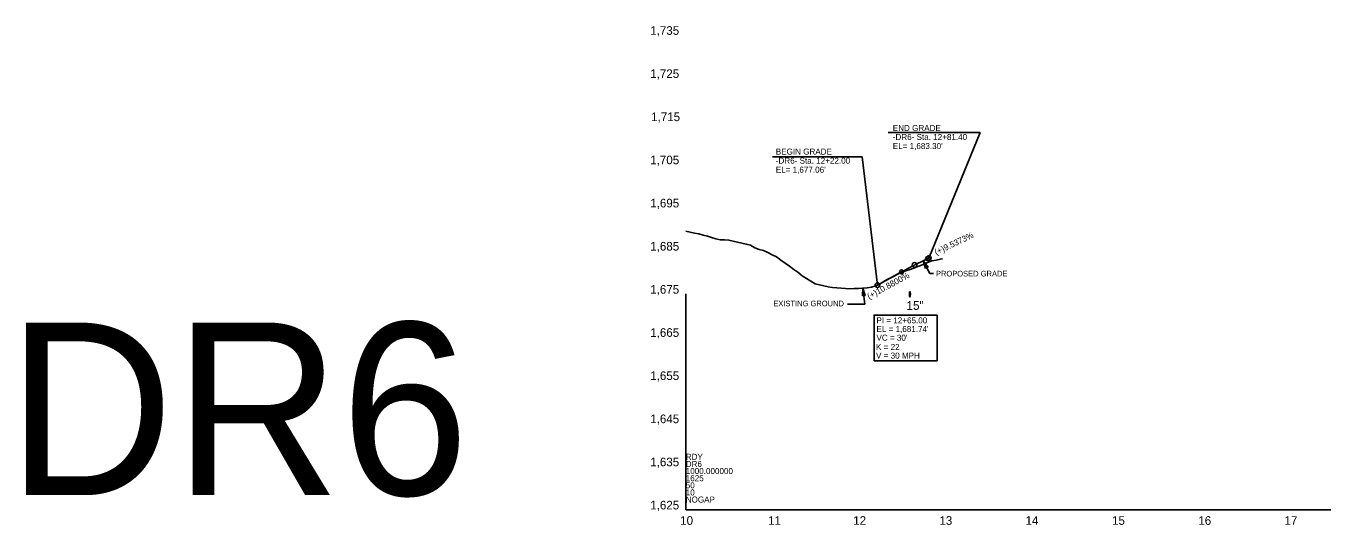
# Model space of a CAD drawing. Extents: x 498575 to 532350, y 405181 to 484585.
# Drawn here: x 526520 to 528031, y 469470 to 470048 of the extents above; entities that cross this region are included whole.
import ezdxf

# ---------------------------------------------------------------- set-up
doc = ezdxf.new("R2010")
doc.units = 0
for name, color, linetype in [('Exist Profile Cell', 7, 'Continuous'), ('Exist Vertical Profile Ground Line', 7, 'Continuous'), ('Exist Vertical Profile Horizontal Axis Label Major', 7, 'Continuous'), ('Exist Vertical Profile Vertical Axis Label', 7, 'Continuous'), ('Prop Drainage Structure Pipe Welded Steel 54in Label', 7, 'Continuous'), ('Prop Grid Mask', 7, 'Continuous'), ('Prop PFL Text', 7, 'Continuous'), ('Prop Vertical Profile Curve Label', 7, 'Continuous'), ('Prop Vertical Profile Grade', 7, 'Continuous'), ('Prop Vertical Profile Grade Label', 7, 'Continuous'), ('Prop VPI Label', 7, 'Continuous'), ('Scratch_Level_7', 7, 'Continuous')]:
    doc.layers.add(name, color=color, linetype=linetype)

msp = doc.modelspace()

# ---------------------------------------------------------------- linework, layer by layer
at = {"layer": 'Exist Profile Cell'}
for q in [(527283.8, 469737.3), (528031, 469487.3), (527283.8, 469487.3)]:
    msp.add_line((527283.8, 469487.3), q, dxfattribs=at)
at = {"layer": 'Exist Vertical Profile Ground Line'}
msp.add_lwpolyline([(527283.8, 469810.2), (527288.8, 469809.1), (527293.8, 469807.9), (527298.8, 469806.8), (527303.8, 469805.6), (527308.8, 469804.1), (527313.8, 469802.6), (527318.8, 469801.3), (527323.8, 469800.1), (527328.8, 469800), (527333.8, 469799.8), (527338.8, 469798.6), (527343.8, 469797.4), (527348.8, 469796.3), (527353.8, 469795.2), (527358.8, 469793.7), (527363.8, 469790.9), (527368.8, 469789), (527373.8, 469787.6), (527378.8, 469785.4), (527383.8, 469782.7), (527388.8, 469780.2), (527393.8, 469776.5), (527398.8, 469773), (527403.8, 469769.5), (527408.8, 469765.7), (527413.8, 469762.6), (527418.8, 469758.5), (527423.8, 469755.3), (527428.8, 469752), (527433.8, 469749.1), (527438.8, 469747.9), (527443.8, 469746.7), (527448.8, 469745.7), (527453.8, 469744.9), (527458.8, 469744.4), (527463.8, 469743.9), (527468.8, 469743.6), (527473.8, 469743.3), (527478.8, 469743.5), (527483.8, 469743.7), (527488.8, 469744.2), (527493.8, 469744.5), (527498.8, 469745.1), (527503.8, 469746.6), (527508.8, 469749.2), (527513.8, 469752.1), (527518.8, 469754.7), (527523.8, 469757.3), (527528.8, 469759.9), (527533.8, 469762.5), (527538.8, 469764.2), (527543.8, 469765.8), (527548.8, 469767.6), (527553.8, 469769.5), (527558.8, 469771.5), (527563.8, 469773.7), (527568.8, 469775.6), (527573.8, 469776.6), (527578.8, 469777.7), (527581.3, 469778.2)], dxfattribs=at)
at = {"layer": 'Prop Drainage Structure Pipe Welded Steel 54in Label'}
msp.add_ellipse((527543.4, 469737), major_axis=(0, 3.12), ratio=0.2, dxfattribs=at)
at = {"layer": 'Prop Grid Mask'}
msp.add_lwpolyline([(527502, 469659.8), (527575, 469659.8), (527575, 469712.9), (527502, 469712.9)], close=True, dxfattribs=at)
at = {"layer": 'Prop PFL Text'}
for p, q in [((527558.6, 469775.7), (527566.5, 469761.2)), ((527570.6, 469761.2), (527566.5, 469761.2)), ((527491.4, 469725.5), (527488.8, 469744.2)), ((527471, 469725.5), (527491.4, 469725.5))]:
    msp.add_line(p, q, dxfattribs=at)
for points in [[(527561.6, 469767), (527558.6, 469775.7), (527564.4, 469768.5), (527562.4, 469768.7)], [(527488.5, 469735), (527488.8, 469744.2), (527491.6, 469735.4), (527489.9, 469736.3)]]:
    msp.add_lwpolyline(points, close=True, dxfattribs=at)
at = {"layer": 'Prop Vertical Profile Curve Label'}
for centre in [(527563.8, 469778.2), (527533.8, 469762.9)]:
    msp.add_circle(centre, 2.25, dxfattribs=at)
at = {"layer": 'Prop Vertical Profile Grade'}
for p, q in [((527563.8, 469778.2), (527565.2, 469778.8)), ((527505.8, 469747.6), (527533.8, 469762.9))]:
    msp.add_line(p, q, dxfattribs=at)
msp.add_spline([(527533.8, 469762.9), (527534.4, 469763.2), (527535, 469763.5), (527535.6, 469763.8), (527536.2, 469764.2), (527536.8, 469764.5), (527537.4, 469764.8), (527538, 469765.1), (527538.6, 469765.4), (527539.2, 469765.8), (527539.8, 469766.1), (527540.4, 469766.4), (527541, 469766.7), (527541.6, 469767), (527542.2, 469767.3), (527542.8, 469767.7), (527543.4, 469768), (527544, 469768.3), (527544.6, 469768.6), (527545.2, 469768.9), (527545.8, 469769.2), (527546.4, 469769.5), (527547, 469769.8), (527547.6, 469770.1), (527548.2, 469770.5), (527548.8, 469770.8), (527549.4, 469771.1), (527550, 469771.4), (527550.6, 469771.7), (527551.2, 469772), (527551.8, 469772.3), (527552.4, 469772.6), (527553, 469772.9), (527553.6, 469773.2), (527554.2, 469773.5), (527554.8, 469773.8), (527555.4, 469774.1), (527556, 469774.4), (527556.6, 469774.7), (527557.2, 469775), (527557.8, 469775.3), (527558.4, 469775.6), (527559, 469775.9), (527559.6, 469776.1), (527560.2, 469776.4), (527560.8, 469776.7), (527561.4, 469777), (527562, 469777.3), (527562.6, 469777.6), (527563.2, 469777.9), (527563.8, 469778.2)], degree=3, dxfattribs=at)
at = {"layer": 'Prop VPI Label'}
for p, q in [((527518.2, 469924.6), (527624.7, 469924.6)), ((527565.2, 469778.8), (527624.7, 469924.6)), ((527384.4, 469896.3), (527488, 469896.3)), ((527488, 469896.3), (527505.8, 469747.6)), ((527533.8, 469762.9), (527546.4, 469769.7)), ((527563.8, 469778.2), (527551.3, 469772.2))]:
    msp.add_line(p, q, dxfattribs=at)
for centre in [(527565.2, 469778.8), (527548.8, 469771), (527505.8, 469747.6)]:
    msp.add_circle(centre, 2.75, dxfattribs=at)

# ---------------------------------------------------------------- texts
at = {"layer": 'Exist Profile Cell'}
for s, p in [('RDY', (527283.8, 469545.1)), ('DR6', (527283.8, 469536.8)), ('1000.000000', (527283.8, 469528.6)), ('1625', (527283.8, 469520.3)), ('50', (527283.8, 469512.1)), ('10', (527283.8, 469503.8)), ('NOGAP', (527283.8, 469495.6))]:
    msp.add_text(s, height=7, dxfattribs=at).set_placement(p)
at = {"layer": 'Exist Vertical Profile Horizontal Axis Label Major'}
for s, p in [('10', (527277.4, 469469.8)), ('11', (527379.2, 469469.8)), ('12', (527477.8, 469469.8)), ('13', (527577.6, 469469.8)), ('14', (527677.4, 469469.8)), ('15', (527777.5, 469469.8)), ('16', (527877.5, 469469.8)), ('17', (527977.3, 469469.8))]:
    msp.add_text(s, height=10, dxfattribs=at).set_placement(p)
at = {"layer": 'Exist Vertical Profile Vertical Axis Label'}
for s, p in [('1,735', (527242.7, 470037.6)), ('1,725', (527242.7, 469987.6)), ('1,715', (527243.8, 469937.6)), ('1,705', (527242.7, 469887.6)), ('1,695', (527242.7, 469837.6)), ('1,685', (527242.7, 469787.6)), ('1,675', (527242.7, 469737.6)), ('1,665', (527242.7, 469687.6)), ('1,655', (527242.7, 469637.6)), ('1,645', (527242.7, 469587.6)), ('1,635', (527242.7, 469537.6)), ('1,625', (527242.7, 469487.6))]:
    msp.add_text(s, height=10, dxfattribs=at).set_placement(p)
at = {"layer": 'Prop Drainage Structure Pipe Welded Steel 54in Label'}
msp.add_text('15"', height=10.12, dxfattribs=at).set_placement((527539.5, 469718.9))
at = {"layer": 'Prop PFL Text'}
for s, p in [('PROPOSED GRADE', (527573.6, 469757.6)), ('EXISTING GROUND', (527385.2, 469723))]:
    msp.add_text(s, height=6.516, dxfattribs=at).set_placement(p)
at = {"layer": 'Prop Vertical Profile Curve Label'}
msp.add_text('V = 30 MPH ', height=7, dxfattribs=at).set_placement((527504.2, 469662.4))
at = {"layer": 'Prop Vertical Profile Grade Label'}
for s, rotation, p in [('(+)9.5373%', 25.4948, (527573.9, 469782.1)), ('(+)10.8800%', 28.5462, (527496.3, 469730.9))]:
    msp.add_text(s, height=7, rotation=rotation, dxfattribs=at).set_placement(p)
at = {"layer": 'Prop VPI Label'}
for s, p in [('END GRADE', (527523.6, 469926.2)), ('-DR6- Sta. 12+81.40', (527523.6, 469915.7)), ('BEGIN GRADE', (527388.1, 469898.8)), ("EL= 1,683.30'", (527523.6, 469905.2)), ('-DR6- Sta. 12+22.00', (527388.1, 469888.3)), ("EL= 1,677.06'", (527388.1, 469877.8)), ('PI = 12+65.00', (527504.7, 469703.2)), ("EL = 1,681.74'", (527504.7, 469693.2)), ("VC = 30'", (527504.7, 469683.1)), ('K = 22', (527504.2, 469672.4))]:
    msp.add_text(s, height=7, dxfattribs=at).set_placement(p)
at = {"layer": 'Scratch_Level_7'}
msp.add_text('DR6', height=200, dxfattribs=at).set_placement((526497.8, 469504.2))

doc.saveas('drawing.dxf')
